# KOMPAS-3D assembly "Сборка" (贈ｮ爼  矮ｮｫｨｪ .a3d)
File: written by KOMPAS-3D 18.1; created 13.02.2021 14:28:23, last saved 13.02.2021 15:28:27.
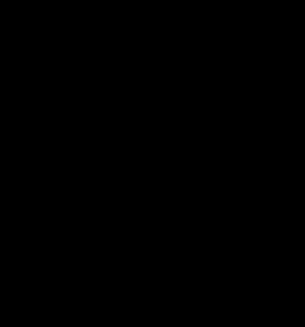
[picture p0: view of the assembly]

Document properties: Полное имя файла: C:\GoogleDrive\НИР\ИКИ\Компас\Сборка столика.a3d

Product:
- Part/product: Сборка
    Масса: 0.642195
  - Component [detail]: Деталь  | Масса: 0.00232462; source file: Сетка.m3d
  - Component [detail]: Зеркало  | Материал: Стекло БК10  ГОСТ 3514-94 (density 3120 kg/m3); Масса: 0.0382404; source file: Зеркало.m3d
  - Component [detail]: Пластиковая стойка  | qty 9  | Масса: 0.00201949; source file: Пластиковая стойка.m3d
  - Component [detail]: Деталь  | Масса: 0.583454; source file: Столик.m3d

Referenced files in C:\GoogleDrive\НИР\ИКИ\Компас\: Столик.m3d, Пластиковая стойка.m3d, Зеркало.m3d, Сетка.m3d
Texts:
  Пластиковая стойка Пластиковая стойка (1)
  Пластиковая стойка Пластиковая стойка (2)
  Пластиковая стойка Пластиковая стойка (3)
  Пластиковая стойка Пластиковая стойка (4)
  Пластиковая стойка Пластиковая стойка (5)
  Пластиковая стойка Пластиковая стойка (6)
  Пластиковая стойка Пластиковая стойка (7)
  Пластиковая стойка Пластиковая стойка (8)
  Пластиковая стойка Пластиковая стойка (9)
